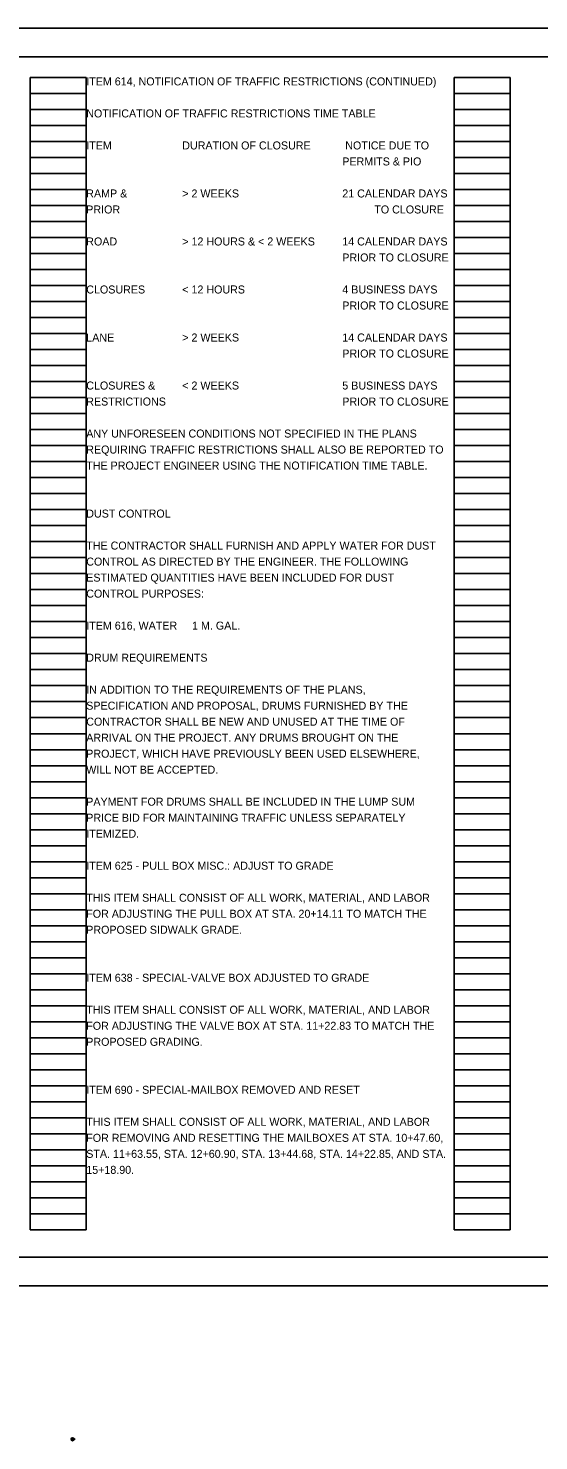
# Model space of a CAD drawing. Extents: x 0 to 1381193, y -3 to 468856.
# Drawn here: x 16.23 to 25.16, y -2.71 to 22 of the extents above; entities that cross this region are included whole.
import ezdxf

# ---------------------------------------------------------------- set-up
doc = ezdxf.new("R2010")
doc.units = 0
for name, color, linetype in [('Default', 7, 'Continuous'), ('SV_P_Mon_Cells_Set', 7, 'Continuous'), ('SV_X_Mon_Cells_Found', 7, 'Continuous'), ('SV_X_Random_Point', 7, 'Continuous'), ('SV_X_Shot_Marker', 7, 'Continuous')]:
    doc.layers.add(name, color=color, linetype=linetype)

msp = doc.modelspace()

# ---------------------------------------------------------------- linework, layer by layer
at = {"layer": 'Default'}
for p, q in [((16.974, -2.683), (17.026, -2.683)), ((17, -2.683), (17.049, -2.683))]:
    msp.add_line(p, q, dxfattribs=at)
msp.add_circle((17, -2.683), 0.026, dxfattribs=at)
at = {"layer": 'SV_P_Mon_Cells_Set'}
msp.add_lwpolyline([(0, 0), (34, 0), (34, 22), (0, 22)], close=True, dxfattribs=at)
at = {"layer": 'SV_X_Mon_Cells_Found'}
msp.add_lwpolyline([(1.5, 21.5), (33.5, 21.5), (33.5, 0.5), (1.5, 0.5)], close=True, dxfattribs=at)
at = {"layer": 'SV_X_Shot_Marker'}
for p, q in [((16.26, 0.98), (16.26, 21.14)), ((16.26, 21.14), (17.24, 21.14)), ((17.24, 0.98), (17.24, 21.14)), ((23.68, 0.98), (23.68, 21.14)), ((23.68, 21.14), (24.66, 21.14)), ((24.66, 0.98), (24.66, 21.14)), ((16.26, 20.86), (17.24, 20.86)), ((23.68, 20.86), (24.66, 20.86)), ((16.26, 20.58), (17.24, 20.58)), ((23.68, 20.58), (24.66, 20.58)), ((16.26, 20.3), (17.24, 20.3)), ((23.68, 20.3), (24.66, 20.3)), ((16.26, 20.02), (17.24, 20.02)), ((23.68, 20.02), (24.66, 20.02)), ((16.26, 19.74), (17.24, 19.74)), ((23.68, 19.74), (24.66, 19.74)), ((16.26, 19.46), (17.24, 19.46)), ((23.68, 19.46), (24.66, 19.46)), ((16.26, 19.18), (17.24, 19.18)), ((23.68, 19.18), (24.66, 19.18)), ((16.26, 18.9), (17.24, 18.9)), ((23.68, 18.9), (24.66, 18.9)), ((16.26, 18.62), (17.24, 18.62)), ((23.68, 18.62), (24.66, 18.62)), ((16.26, 18.34), (17.24, 18.34)), ((23.68, 18.34), (24.66, 18.34)), ((16.26, 18.06), (17.24, 18.06)), ((23.68, 18.06), (24.66, 18.06)), ((16.26, 17.78), (17.24, 17.78)), ((23.68, 17.78), (24.66, 17.78)), ((16.26, 17.5), (17.24, 17.5)), ((23.68, 17.5), (24.66, 17.5)), ((16.26, 17.22), (17.24, 17.22)), ((23.68, 17.22), (24.66, 17.22)), ((16.26, 16.94), (17.24, 16.94)), ((23.68, 16.94), (24.66, 16.94)), ((16.26, 16.66), (17.24, 16.66)), ((23.68, 16.66), (24.66, 16.66)), ((16.26, 16.38), (17.24, 16.38)), ((23.68, 16.38), (24.66, 16.38)), ((16.26, 16.1), (17.24, 16.1)), ((23.68, 16.1), (24.66, 16.1)), ((16.26, 15.82), (17.24, 15.82)), ((23.68, 15.82), (24.66, 15.82)), ((16.26, 15.54), (17.24, 15.54)), ((23.68, 15.54), (24.66, 15.54)), ((16.26, 15.26), (17.24, 15.26)), ((23.68, 15.26), (24.66, 15.26)), ((16.26, 14.98), (17.24, 14.98)), ((23.68, 14.98), (24.66, 14.98)), ((16.26, 14.7), (17.24, 14.7)), ((23.68, 14.7), (24.66, 14.7)), ((16.26, 14.42), (17.24, 14.42)), ((23.68, 14.42), (24.66, 14.42)), ((16.26, 14.14), (17.24, 14.14)), ((23.68, 14.14), (24.66, 14.14)), ((16.26, 13.86), (17.24, 13.86)), ((23.68, 13.86), (24.66, 13.86)), ((16.26, 13.58), (17.24, 13.58)), ((23.68, 13.58), (24.66, 13.58)), ((16.26, 13.3), (17.24, 13.3)), ((23.68, 13.3), (24.66, 13.3)), ((16.26, 13.02), (17.24, 13.02)), ((23.68, 13.02), (24.66, 13.02)), ((16.26, 12.74), (17.24, 12.74)), ((23.68, 12.74), (24.66, 12.74)), ((16.26, 12.46), (17.24, 12.46)), ((23.68, 12.46), (24.66, 12.46)), ((16.26, 12.18), (17.24, 12.18)), ((23.68, 12.18), (24.66, 12.18)), ((16.26, 11.9), (17.24, 11.9)), ((23.68, 11.9), (24.66, 11.9)), ((16.26, 11.62), (17.24, 11.62)), ((23.68, 11.62), (24.66, 11.62)), ((16.26, 11.34), (17.24, 11.34)), ((23.68, 11.34), (24.66, 11.34)), ((16.26, 11.06), (17.24, 11.06)), ((23.68, 11.06), (24.66, 11.06)), ((16.26, 10.78), (17.24, 10.78)), ((23.68, 10.78), (24.66, 10.78)), ((16.26, 10.5), (17.24, 10.5)), ((23.68, 10.5), (24.66, 10.5)), ((16.26, 10.22), (17.24, 10.22)), ((23.68, 10.22), (24.66, 10.22)), ((16.26, 9.94), (17.24, 9.94)), ((23.68, 9.94), (24.66, 9.94)), ((16.26, 9.66), (17.24, 9.66)), ((23.68, 9.66), (24.66, 9.66)), ((16.26, 9.38), (17.24, 9.38)), ((23.68, 9.38), (24.66, 9.38)), ((16.26, 9.1), (17.24, 9.1)), ((23.68, 9.1), (24.66, 9.1)), ((16.26, 8.82), (17.24, 8.82)), ((23.68, 8.82), (24.66, 8.82)), ((16.26, 8.54), (17.24, 8.54)), ((23.68, 8.54), (24.66, 8.54)), ((16.26, 8.26), (17.24, 8.26)), ((23.68, 8.26), (24.66, 8.26)), ((16.26, 7.98), (17.24, 7.98)), ((23.68, 7.98), (24.66, 7.98)), ((16.26, 7.7), (17.24, 7.7)), ((23.68, 7.7), (24.66, 7.7)), ((16.26, 7.42), (17.24, 7.42)), ((23.68, 7.42), (24.66, 7.42)), ((16.26, 7.14), (17.24, 7.14)), ((23.68, 7.14), (24.66, 7.14)), ((16.26, 6.86), (17.24, 6.86)), ((23.68, 6.86), (24.66, 6.86)), ((16.26, 6.58), (17.24, 6.58)), ((23.68, 6.58), (24.66, 6.58)), ((16.26, 6.3), (17.24, 6.3)), ((23.68, 6.3), (24.66, 6.3)), ((16.26, 6.02), (17.24, 6.02)), ((23.68, 6.02), (24.66, 6.02)), ((16.26, 5.74), (17.24, 5.74)), ((23.68, 5.74), (24.66, 5.74)), ((16.26, 5.46), (17.24, 5.46)), ((23.68, 5.46), (24.66, 5.46)), ((16.26, 5.18), (17.24, 5.18)), ((23.68, 5.18), (24.66, 5.18)), ((16.26, 4.9), (17.24, 4.9)), ((23.68, 4.9), (24.66, 4.9)), ((16.26, 4.62), (17.24, 4.62)), ((23.68, 4.62), (24.66, 4.62)), ((16.26, 4.34), (17.24, 4.34)), ((23.68, 4.34), (24.66, 4.34)), ((16.26, 4.06), (17.24, 4.06)), ((23.68, 4.06), (24.66, 4.06)), ((16.26, 3.78), (17.24, 3.78)), ((23.68, 3.78), (24.66, 3.78)), ((16.26, 3.5), (17.24, 3.5)), ((23.68, 3.5), (24.66, 3.5)), ((16.26, 3.22), (17.24, 3.22)), ((23.68, 3.22), (24.66, 3.22)), ((16.26, 2.94), (17.24, 2.94)), ((23.68, 2.94), (24.66, 2.94)), ((16.26, 2.66), (17.24, 2.66)), ((23.68, 2.66), (24.66, 2.66)), ((16.26, 2.38), (17.24, 2.38)), ((23.68, 2.38), (24.66, 2.38)), ((16.26, 2.1), (17.24, 2.1)), ((23.68, 2.1), (24.66, 2.1)), ((16.26, 1.82), (17.24, 1.82)), ((23.68, 1.82), (24.66, 1.82)), ((16.26, 1.54), (17.24, 1.54)), ((23.68, 1.54), (24.66, 1.54)), ((16.26, 1.26), (17.24, 1.26)), ((23.68, 1.26), (24.66, 1.26)), ((16.26, 0.98), (17.24, 0.98)), ((23.68, 0.98), (24.66, 0.98))]:
    msp.add_line(p, q, dxfattribs=at)

# ---------------------------------------------------------------- texts
at = {"layer": 'Default'}
for s, p in [('1', (16.999, -2.676)), ('4', (16.999, -2.693)), ('Drawing', (17.032, -2.676)), ('1:1', (17.032, -2.693))]:
    msp.add_text(s, height=0.00328, dxfattribs=at).set_placement(p)
at = {"layer": 'SV_X_Random_Point'}
for s, p in [('ITEM 614, NOTIFICATION OF TRAFFIC RESTRICTIONS (CONTINUED)', (17.24, 21)), ('NOTIFICATION OF TRAFFIC RESTRICTIONS TIME TABLE', (17.24, 20.44)), ('ITEM', (17.24, 19.88)), ('DURATION OF CLOSURE    ', (18.92, 19.88)), (' NOTICE DUE TO', (21.72, 19.88)), ('PERMITS & PIO', (21.72, 19.6)), ('RAMP &', (17.24, 19.04)), ('> 2 WEEKS', (18.92, 19.04)), ('21 CALENDAR DAYS ', (21.72, 19.04)), ('PRIOR ', (17.24, 18.76)), ('TO CLOSURE', (22.28, 18.76)), ('ROAD', (17.24, 18.2)), ('> 12 HOURS & < 2 WEEKS', (18.92, 18.2)), ('14 CALENDAR DAYS ', (21.72, 18.2)), ('PRIOR TO CLOSURE', (21.72, 17.92)), ('CLOSURES', (17.24, 17.36)), ('< 12 HOURS', (18.92, 17.36)), ('4 BUSINESS DAYS ', (21.72, 17.36)), ('PRIOR TO CLOSURE', (21.72, 17.08)), ('LANE', (17.24, 16.52)), ('> 2 WEEKS', (18.92, 16.52)), ('14 CALENDAR DAYS ', (21.72, 16.52)), ('PRIOR TO CLOSURE', (21.72, 16.24)), ('CLOSURES &', (17.24, 15.68)), ('< 2 WEEKS', (18.92, 15.68)), ('5 BUSINESS DAYS ', (21.72, 15.68)), ('RESTRICTIONS', (17.24, 15.4)), ('PRIOR TO CLOSURE', (21.72, 15.4)), ('ANY UNFORESEEN CONDITIONS NOT SPECIFIED IN THE PLANS ', (17.24, 14.84)), ('REQUIRING TRAFFIC RESTRICTIONS SHALL ALSO BE REPORTED TO ', (17.24, 14.56)), ('THE PROJECT ENGINEER USING THE NOTIFICATION TIME TABLE.', (17.24, 14.28)), ('DUST CONTROL', (17.24, 13.44)), ('THE CONTRACTOR SHALL FURNISH AND APPLY WATER FOR DUST', (17.24, 12.88)), ('CONTROL AS DIRECTED BY THE ENGINEER. THE FOLLOWING', (17.24, 12.6)), ('ESTIMATED QUANTITIES HAVE BEEN INCLUDED FOR DUST', (17.24, 12.32)), ('CONTROL PURPOSES:', (17.24, 12.04)), ('ITEM 616, WATER     1 M. GAL.', (17.24, 11.48)), ('DRUM REQUIREMENTS', (17.24, 10.92)), ('IN ADDITION TO THE REQUIREMENTS OF THE PLANS,', (17.24, 10.36)), ('SPECIFICATION AND PROPOSAL, DRUMS FURNISHED BY THE', (17.24, 10.08)), ('CONTRACTOR SHALL BE NEW AND UNUSED AT THE TIME OF', (17.24, 9.8)), ('ARRIVAL ON THE PROJECT. ANY DRUMS BROUGHT ON THE', (17.24, 9.52)), ('PROJECT, WHICH HAVE PREVIOUSLY BEEN USED ELSEWHERE,', (17.24, 9.24)), ('WILL NOT BE ACCEPTED.', (17.24, 8.96)), ('PAYMENT FOR DRUMS SHALL BE INCLUDED IN THE LUMP SUM', (17.24, 8.4)), ('PRICE BID FOR MAINTAINING TRAFFIC UNLESS SEPARATELY', (17.24, 8.12)), ('ITEMIZED.', (17.24, 7.84)), ('ITEM 625 - PULL BOX MISC.: ADJUST TO GRADE', (17.24, 7.28)), ('THIS ITEM SHALL CONSIST OF ALL WORK, MATERIAL, AND LABOR ', (17.24, 6.72)), ('FOR ADJUSTING THE PULL BOX AT STA. 20+14.11 TO MATCH THE ', (17.24, 6.44)), ('PROPOSED SIDWALK GRADE.', (17.24, 6.16)), ('ITEM 638 - SPECIAL-VALVE BOX ADJUSTED TO GRADE', (17.24, 5.32)), ('THIS ITEM SHALL CONSIST OF ALL WORK, MATERIAL, AND LABOR ', (17.24, 4.76)), ('FOR ADJUSTING THE VALVE BOX AT STA. 11+22.83 TO MATCH THE ', (17.24, 4.48)), ('PROPOSED GRADING.', (17.24, 4.2)), ('ITEM 690 - SPECIAL-MAILBOX REMOVED AND RESET', (17.24, 3.36)), ('THIS ITEM SHALL CONSIST OF ALL WORK, MATERIAL, AND LABOR ', (17.24, 2.8)), ('FOR REMOVING AND RESETTING THE MAILBOXES AT STA. 10+47.60, ', (17.24, 2.52)), ('STA. 11+63.55, STA. 12+60.90, STA. 13+44.68, STA. 14+22.85, AND STA. ', (17.24, 2.24)), ('15+18.90.', (17.24, 1.96))]:
    msp.add_text(s, height=0.14, dxfattribs=at).set_placement(p)

doc.saveas('drawing.dxf')
